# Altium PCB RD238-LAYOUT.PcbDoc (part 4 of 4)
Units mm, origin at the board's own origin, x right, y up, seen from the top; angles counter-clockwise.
Board outline 100 x 120 mm, 4 copper layers (Top Layer, GND2, POWER 3, Bottom Layer), stack 1.444 mm thick; 434 components, 174 nets, 1045 pads, 261 vias.
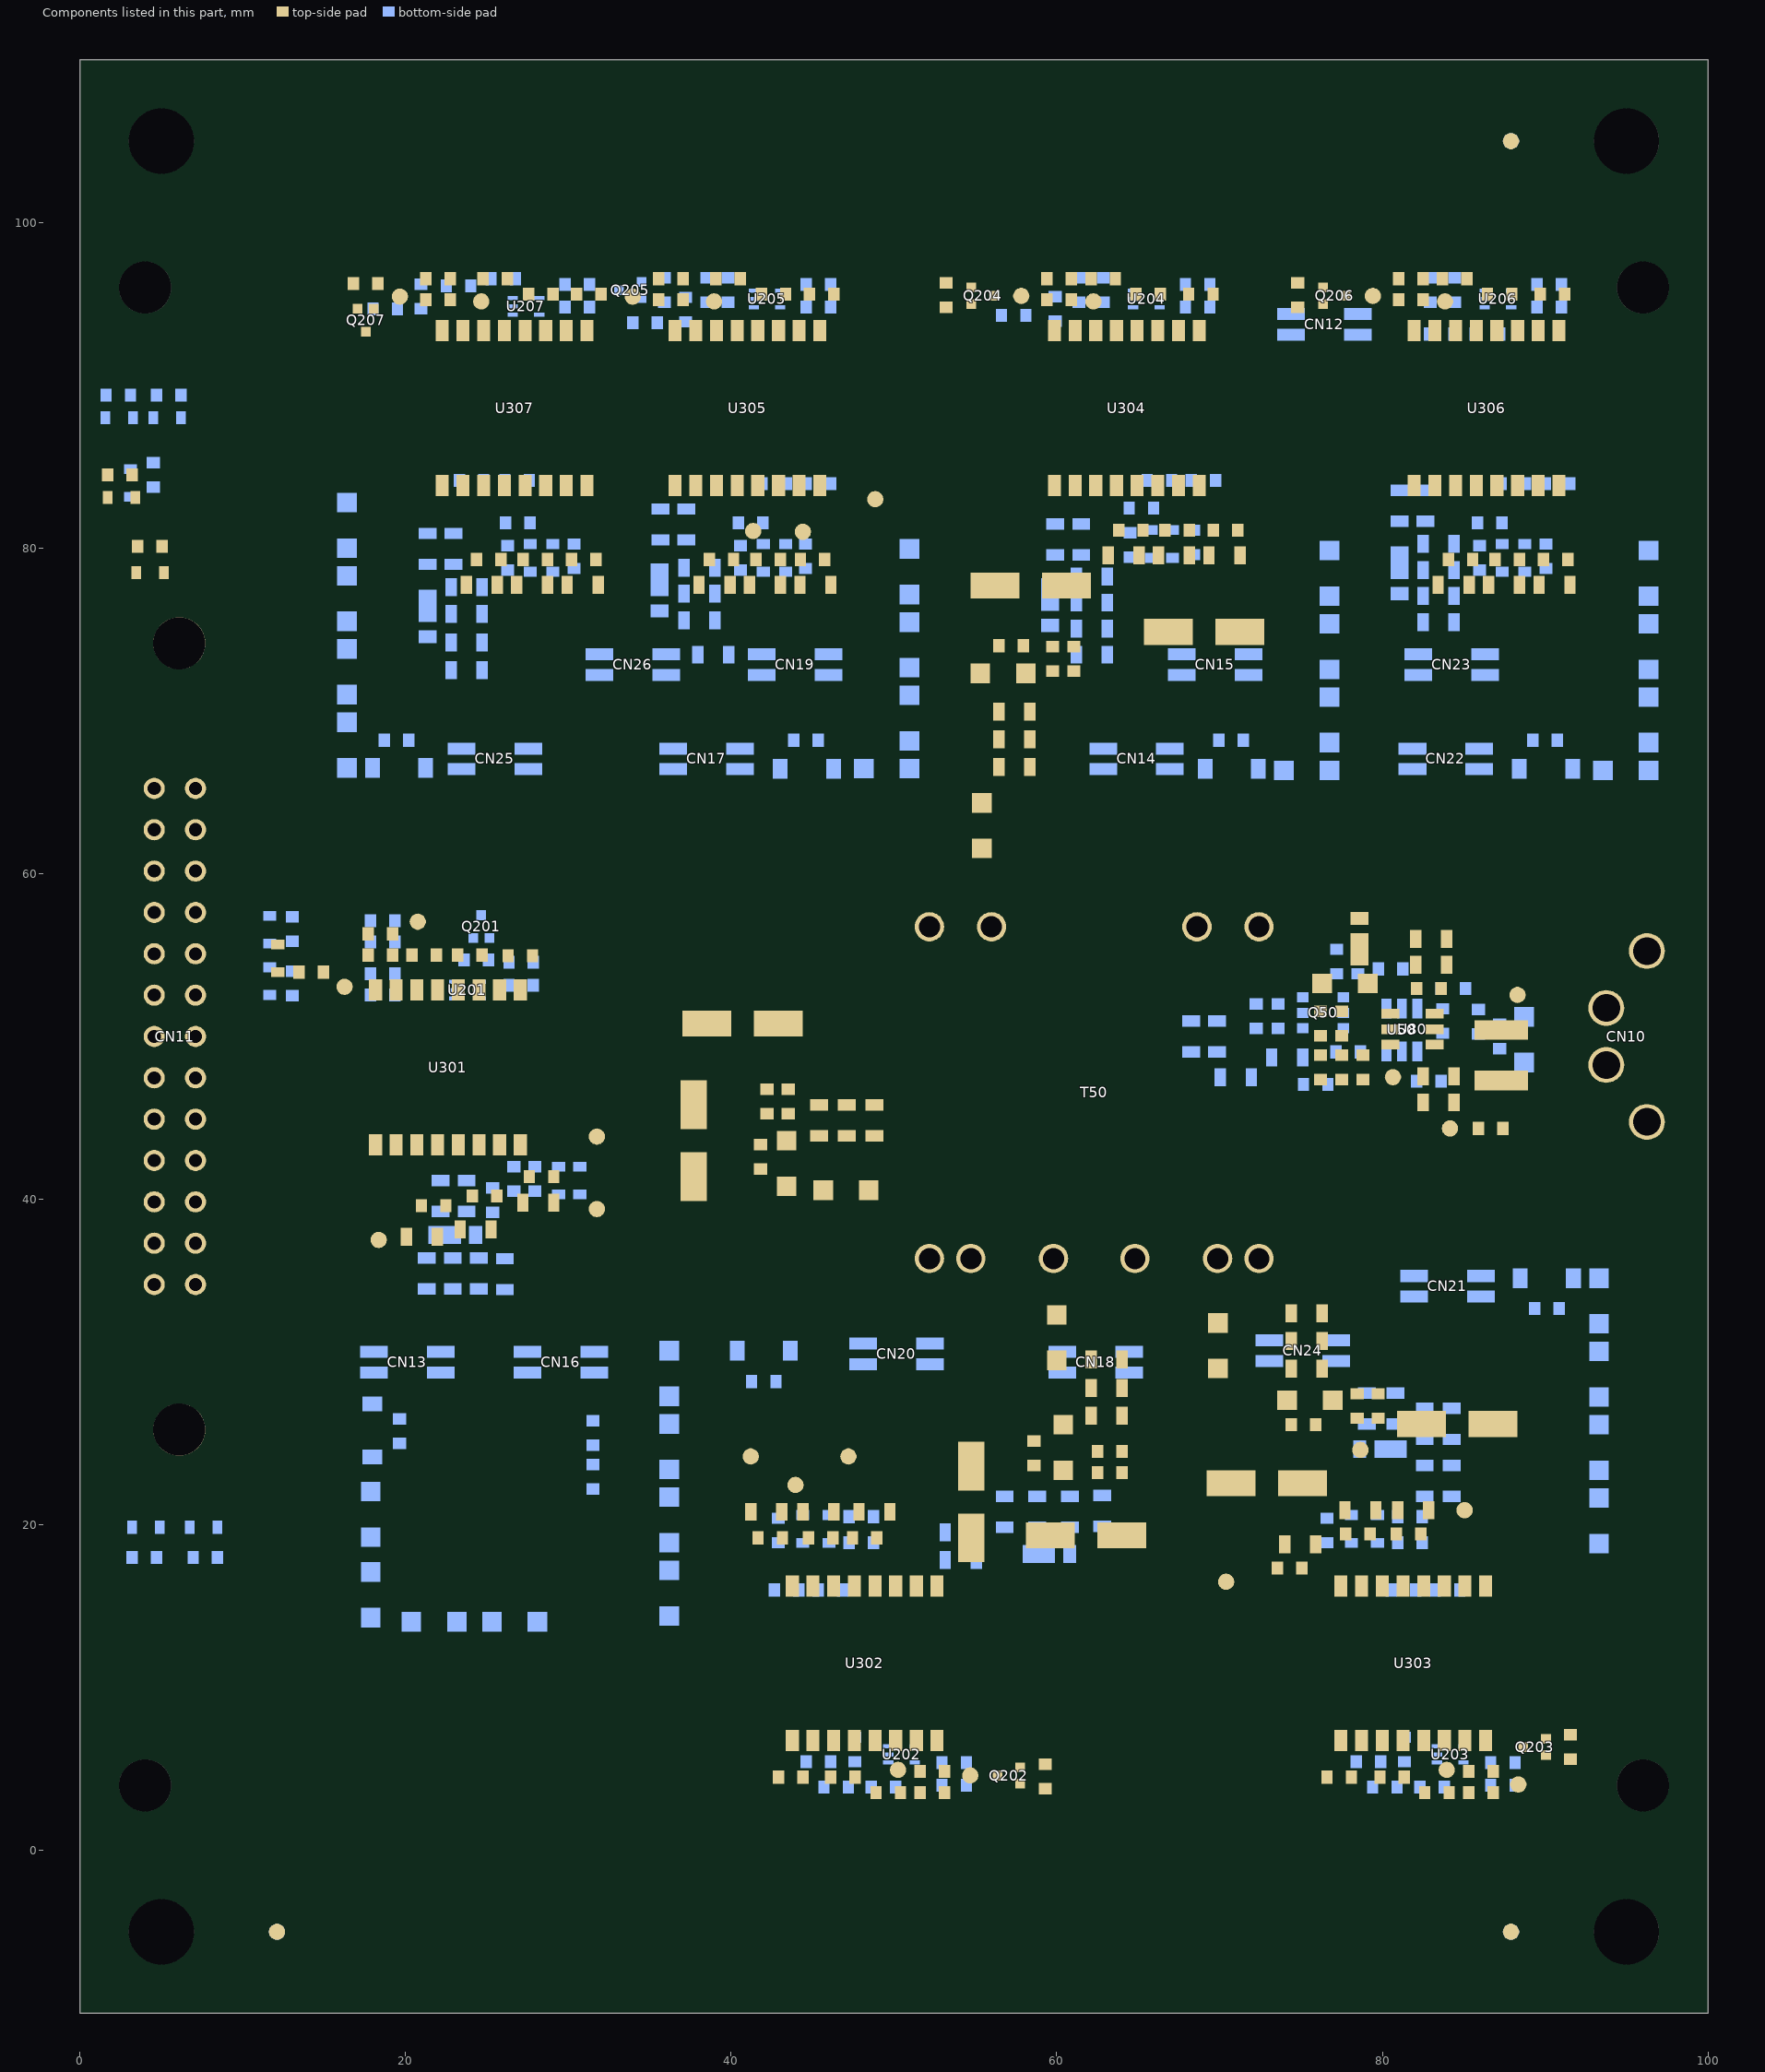
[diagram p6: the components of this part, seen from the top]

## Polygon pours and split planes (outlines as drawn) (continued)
NetD326_2 on Bottom Layer "NONET_L04_P-001" (solid, remove dead copper, pour order 385): 91.3,65.9 91.45,65.75 94,65.75 94.15,65.9 94.15,67.8 93.3,68.65 90.641,68.65 90.473,68.482 90.473,67.927 90.65,67.75 91.1,67.75 91.3,67.55 91.3,67.25
GND on Bottom Layer "NONET_L04_P-001" (solid, remove dead copper, pour order 376): 24.35,56.45 22.9,56.45 22.8,56.35 22.8,55.75 22,54.95 22,53.9 22.2,53.7 23.55,53.7 23.9,54.05 23.9,55.3 24.45,55.85 24.45,56.35
GND on Bottom Layer "NONET_L04_P-001" (solid, remove dead copper, pour order 375): 21 vertices, not listed, extent 10.05,53.45 18.15,56.2
NetR301_1 on Bottom Layer "NONET_L04_P-001" (solid, remove dead copper, pour order 369): 19 vertices, not listed, extent 19.7,40.25 27.05,43.8
NetC321_2 on Bottom Layer "NONET_L04_P-001" (solid, remove dead copper, pour order 368): 24 vertices, not listed, extent 24.95,37.2 31.2,40.8
NetD331_1 on Bottom Layer "NONET_L04_P-001" (solid, remove dead copper, pour order 365): 20.725,13.6 20.525,13.4 17.775,13.4 17.625,13.55 17.625,14.75 17.854,14.979 20.546,14.979 20.725,14.8
NetD341_1 on Bottom Layer "NONET_L04_P-001" (solid, remove dead copper, pour order 364): 25.575,13.6 25.475,13.5 23.025,13.5 22.875,13.65 22.875,14.6 22.975,14.7 25.475,14.7 25.575,14.6
NetD321_1 on Bottom Layer "NONET_L04_P-001" (solid, remove dead copper, pour order 363): 17.4,16.7 17.25,16.85 17.25,19.65 17.4,19.8 18.35,19.8 18.45,19.7 18.45,16.85 18.3,16.7
NetD342_1 on Bottom Layer "NONET_L04_P-001" (solid, remove dead copper, pour order 358): 35.7,16.75 35.6,16.85 35.6,19.3 35.75,19.45 36.7,19.45 36.8,19.35 36.8,16.85 36.7,16.75
NetD332_1 on Bottom Layer "NONET_L04_P-001" (solid, remove dead copper, pour order 357): 35.7,21.25 35.6,21.35 35.6,23.8 35.75,23.95 36.7,23.95 36.8,23.85 36.8,21.35 36.7,21.25
NetD322_1 on Bottom Layer "NONET_L04_P-001" (solid, remove dead copper, pour order 356): 35.7,25.75 35.6,25.85 35.6,28.3 35.75,28.45 36.7,28.45 36.8,28.35 36.8,25.85 36.7,25.75
NetD322_2 on Bottom Layer "NONET_L04_P-001" (solid, remove dead copper, pour order 355): 40.4,31.6 40.8,31.2 40.8,29.891 41.5,29.191 41.5,28.5 41.4,28.4 40.05,28.4 38.35,30.1 35.7,30.1 35.55,30.25 35.55,31.35 35.8,31.6
NetD323_2 on Bottom Layer "NONET_L04_P-001" (solid, remove dead copper, pour order 342): 93.75,35.8 93.9,35.65 93.9,34.65 93.8,34.55 92.7,34.55 92.25,34.1 92.25,33.55 91.6,32.9 90.6,32.9 90.5,33 90.5,33.65 91.25,34.4 91.25,35.7 91.35,35.8 91.4,35.8
NetCN21_1 on Bottom Layer "NONET_L04_P-001" (solid, remove dead copper, pour order 341): 88.8,35.75 88.9,35.65 88.9,34.25 89.2,33.95 89.5,33.95 89.65,33.8 89.65,32.95 89.45,32.75 81.45,32.75 81.05,33.15 81.05,35.55 81.25,35.75
NetR303_1 on Bottom Layer "NONET_L04_P-001" (solid, remove dead copper, pour order 339): 86.05,22.1 86.5,21.65 86.5,17.75 85.9,17.15 84.5,17.15 82.5,17.15 81.95,17.7 81.95,22 82.05,22.1
NetD343_1 on Bottom Layer "NONET_L04_P-001" (solid, remove dead copper, pour order 287): 92.8,21.2 92.7,21.3 92.7,23.75 92.85,23.9 93.8,23.9 93.9,23.8 93.9,21.3 93.8,21.2
NetD333_1 on Bottom Layer "NONET_L04_P-001" (solid, remove dead copper, pour order 286): 92.8,25.7 92.7,25.8 92.7,28.25 92.85,28.4 93.8,28.4 93.9,28.3 93.9,25.8 93.8,25.7
NetD323_1 on Bottom Layer "NONET_L04_P-001" (solid, remove dead copper, pour order 285): 92.8,30.2 92.7,30.3 92.7,32.75 92.85,32.9 93.8,32.9 93.9,32.8 93.9,30.3 93.8,30.2
GND on Bottom Layer "NONET_L04_P-001" (solid, remove dead copper, pour order 185): 4.65,20.15 4.65,18.9 4.4,18.65 4.4,17.8 4.65,17.55 6.95,17.55 7.3,17.9 7.3,18.7 7.05,18.95 7.05,20.1 6.85,20.3 4.8,20.3
NetC221_2 on POWER 3 "NONET_L04_P-001" (solid, remove dead copper, pour order 264): 23 vertices, not listed, extent 85.25,0.5 99.15,57.7
NetC334_2 on POWER 3 "2" (solid, remove dead copper, pour order 229): 41 vertices, not listed, extent 25.25,71.2 92.65,85
NetC221_2 on POWER 3 "NONET_L04_P-001" (solid, remove dead copper, pour order 473): 59 vertices, not listed, extent 0.95,1 90.7,99.05
NetC221_2 on POWER 3 "NONET_L04_P-001" (solid, remove dead copper, pour order 216): 26.7,52.05 27.5,52.85 27.5,56.35 27.2,56.65 27.18,56.63 24.461,56.63 22.182,54.35 16.3,54.35 12.875,57.775 12.85,57.7 12.85,52.25 13.05,52.05
no net on POWER 3 "NONET_L03_P613" (solid, pour order 613): 1,109 1,101 99,101 99,109
no net on POWER 3 "NONET_L03_P608" (solid, pour order 608): 1,-1 1,-9 99,-9 99,-1
NetC321_2 on POWER 3 "NONET_L04_P-001" (solid, remove dead copper, pour order 479): 18 vertices, not listed, extent 17.55,30.25 35.45,46
NetC324_1 on POWER 3 "NONET_L04_P-001" (solid, remove dead copper, pour order 234): 18 vertices, not listed, extent 57.15,73.9 73,82
NetC10_2 on POWER 3 "NONET_L04_P-001" (solid, remove dead copper, pour order 263): 82.1,49 84.5,51.4 87.6,51.4 88,51.8 88,55.9 87.4,56.5 82.85,56.5 81.4,55.05 68.2,55.05 67.45,54.3 67.45,50.675 69.125,49
NetC322_2 on POWER 3 "NONET_L04_P-001" (solid, remove dead copper, pour order 180): 43.1,16.2 43.8,15.5 58,15.5 58.55,16.05 58.55,20.9 54.4,25.05 43.45,25.05 43.1,24.7 43.1,24.6
NetC333_2 on POWER 3 "NONET_L04_P-001" (solid, remove dead copper, pour order 167): 70.35,25 68.85,23.5 68.85,16.4 69.75,15.5 82.25,15.5 82.9,16.15 82.9,24.15 82.05,25
GND on GND2 "NONET_L04_P-001" (solid, remove dead copper, pour order 461): 66 vertices, not listed, extent 1.7,1.95 99.1,61.6
NetC322_1 on GND2 "NONET_L04_P-001" (solid, remove dead copper, pour order 179): 65.85,20.15 65.85,15.8 65.55,15.5 43.6,15.5 40.1,19 40.1,23.6 40.8,24.3 54.25,24.3 58.05,20.5 65.5,20.5
GND on GND2 "GND_L02_P689" (solid, pour order 689): 77.45,57.7 77.2,57.45 77.2,55 78.85,55 79.65,55.8 83.8,55.8 84.8,56.8 87.2,56.8 88.15,55.85 90.25,55.85 90.65,56.25 90.65,57.45 90.4,57.7
NetC324_2 on GND2 "NONET_L04_P-001" (solid, remove dead copper, pour order 462): 33 vertices, not listed, extent 28.55,71.2 92.65,85
GND on GND2 "NONET_L04_P-001" (solid, remove dead copper, pour order 460): 33 vertices, not listed, extent 1,54.25 92.293,98.225
NetC10_2 on GND2 "NETC10_2_L02_P684" (solid, remove dead copper, pour order 684): 87,53.6 87.2,53.4 87.2,51.75 86.95,51.5 80.75,51.5 80.2,52.05 80.2,53.309 80.491,53.6
no net on GND2 "NONET_L02_P612" (solid, pour order 612): 1,109 1,101 99,101 99,109
no net on GND2 "NONET_L02_P610" (solid, pour order 610): 1,-1 1,-9 99,-9 99,-1
NetC321_1 on GND2 "NONET_L04_P-001" (solid, remove dead copper, pour order 475): 18 vertices, not listed, extent 17.15,34.05 42.7,56.85
NetC324_1 on GND2 "NONET_L04_P-001" (solid, remove dead copper, pour order 452): 64.2,74.15 63.85,73.8 63.85,72 64.25,71.6 73.17,71.6 73.35,71.78 73.35,78.3 72.75,78.9 71.05,78.9 70.65,78.5 70.65,75.2 69.6,74.15
NetC323_1 on GND2 "NONET_L04_P-001" (solid, remove dead copper, pour order 166): 85.6,21.8 85.6,23.55 85.948,23.898 89.202,23.898 89.55,23.55 89.55,16.4 88.75,15.6 71.85,15.6 71.4,16.05 71.4,19.85 72.75,21.2 85,21.2

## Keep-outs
Keep-Out Layer:
  circle w0.1: c59.8,36.36 r4
  circle w0.1: c64.8,36.36 r4
  circle w0.1: c69.88,36.36 r4
  circle w0.1: c72.42,36.36 r4
  circle w0.1: c52.18,56.74 r4
  circle w0.1: c55.99,56.74 r4
  circle w0.1: c52.18,36.36 r4
  circle w0.1: c72.42,56.74 r4
  circle w0.1: c68.61,56.74 r4
  circle w0.1: c5,105 r3
  circle w0.1: c5,-5 r3
  circle w0.1: c95,-5 r3
  circle w0.1: c95,105 r3
  circle w0.1: c93.75,51.75 r4.3
  circle w0.1: c93.75,48.25 r4.3
  circle w0.1: c4.56,65.24 r3.7
  circle w0.1: c7.1,65.24 r3.7
  circle w0.1: c7.1,57.62 r3.7
  circle w0.1: c7.1,55.08 r3.7
  circle w0.1: c6.1,74.15 r2.1
  circle w0.1: c96.25,55.25 r1.35
  circle w0.1: c96.25,44.75 r1.35
  circle w0.1: c4,4 r4
  circle w0.1: c96,4 r4
  circle w0.1: c4,4 r2.4
  circle w0.1: c96,4 r2.4
  circle w0.1: c96,96 r2.4
  circle w0.1: c96,96 r4
  circle w0.1: c4,96 r2.4
  circle w0.1: c4,96 r4
  lines w1: 0.5,-0.5 99.5,-0.5 ; 0.5,0.5 99.5,0.5 ; 0.5,99.51 99.5,99.51 ; 0.5,100.5 99.5,100.5 ; 23.05,31.55 23.148,31.545 23.34,31.507 23.521,31.432 23.684,31.323 23.823,31.184 23.932,31.021 24.007,30.84 24.045,30.648 24.05,30.55 24.05,18.247 ; 23.05,31.55 23.05,31.55 ; 23.05,31.55 13.868,31.55 13.614,31.618 13.386,31.749 13.199,31.936 13.068,32.164 13,32.418 13,32.682 13.068,32.936 13.199,33.164 13.386,33.351 13.614,33.482 13.868,33.55 14,33.55 23.05,33.55 23.247,33.55 23.637,33.499 24.017,33.397 24.38,33.247 24.72,33.05 25.033,32.811 25.311,32.533 25.55,32.22 25.747,31.88 25.897,31.517 25.999,31.137 26.05,30.747 26.05,30.55 ; 24.05,18.247 24.05,18.051 24.101,17.661 24.203,17.281 24.354,16.918 24.551,16.578 24.79,16.266 25.068,15.989 25.38,15.749 25.721,15.553 26.084,15.403 26.464,15.301 26.853,15.25 29.199,15.25 29.392,15.288 29.574,15.363 29.738,15.473 29.877,15.612 29.987,15.776 30.062,15.958 30.1,16.151 30.1,16.25 30.1,16.349 30.062,16.542 29.987,16.724 29.877,16.888 29.738,17.027 29.574,17.137 29.392,17.212 29.199,17.25 27.05,17.25 26.952,17.255 26.76,17.293 26.579,17.368 26.416,17.477 26.277,17.616 26.168,17.779 26.093,17.96 26.055,18.152 26.05,18.25 26.05,30.55 ; 24.05,18.247 24.05,18.247 ; 26.05,30.55 26.05,30.55 ; 35,31.252 35.005,31.349 35.044,31.541 35.119,31.722 35.228,31.885 35.366,32.023 35.529,32.132 35.71,32.207 35.902,32.245 36,32.25 36.5,32.25 36.599,32.25 36.792,32.288 36.974,32.363 37.138,32.473 37.277,32.612 37.387,32.776 37.462,32.958 37.5,33.151 37.5,33.25 37.5,33.349 37.462,33.542 37.387,33.724 37.277,33.888 37.138,34.027 36.974,34.137 36.792,34.212 36.599,34.25 36,34.25 35.997,34.25 ; 35,31.252 35,31.252 ; 35,31.252 35,11.4 35,11.268 34.932,11.014 34.801,10.786 34.614,10.599 34.386,10.468 34.132,10.4 33.868,10.4 33.614,10.468 33.386,10.599 33.199,10.786 33.068,11.014 33,11.268 33,11.4 33,31.25 33,31.447 33.051,31.836 33.153,32.216 33.303,32.579 33.499,32.92 33.739,33.232 34.016,33.51 34.328,33.749 34.668,33.946 35.031,34.097 35.411,34.199 35.801,34.25 35.997,34.25 ; 35.997,34.25 35.997,34.25 ; 37.615,24.518 37.615,16.9 37.615,16.768 37.683,16.514 37.814,16.286 38.001,16.099 38.229,15.968 38.483,15.9 38.747,15.9 39.001,15.968 39.229,16.099 39.416,16.286 39.547,16.514 39.615,16.768 39.615,16.9 39.615,24.65 39.62,24.748 39.658,24.94 39.733,25.121 39.842,25.284 39.981,25.423 40.144,25.532 40.325,25.607 40.517,25.645 40.615,25.65 40.714,25.65 ; 37.615,24.518 37.615,24.518 ; 37.615,24.518 37.615,24.65 37.615,24.847 37.615,24.85 37.615,24.982 37.65,25.112 37.666,25.237 37.768,25.617 37.918,25.98 38.115,26.32 38.354,26.633 38.632,26.911 38.945,27.15 39.285,27.347 39.648,27.497 40.028,27.599 40.418,27.65 40.483,27.65 ; 40.483,27.65 40.483,27.65 ; 40.483,27.65 52.468,27.65 ; 40.714,25.65 52.699,25.65 ; 40.714,25.65 40.714,25.65 ; 46.803,69.2 46.999,69.2 47.389,69.251 47.769,69.353 48.132,69.504 48.472,69.701 48.784,69.94 49.061,70.218 49.301,70.53 49.497,70.871 49.647,71.234 49.749,71.614 49.8,72.003 49.8,72.2 49.782,72.2 49.8,72.268 49.8,72.4 49.8,80.303 49.8,80.435 49.732,80.689 49.6,80.917 49.414,81.103 49.186,81.235 48.932,81.303 48.668,81.303 48.414,81.235 48.186,81.103 47.999,80.917 47.868,80.689 47.8,80.435 47.8,80.303 47.8,72.4 47.8,72.268 47.818,72.2 47.8,72.2 ; 46.803,69.2 46.803,69.2 ; 46.803,69.2 46.8,69.2 34.5,69.2 34.5,64.7 34.5,64.568 34.432,64.314 34.3,64.086 34.114,63.899 33.886,63.768 33.632,63.7 33.368,63.7 33.114,63.768 32.886,63.899 32.699,64.086 32.568,64.314 32.5,64.568 32.5,64.7 32.5,69.2 20.694,69.2 20.537,69.19 20.16,69.215 19.789,69.289 19.432,69.411 19.093,69.578 18.779,69.789 18.495,70.038 18.246,70.323 18.037,70.637 17.87,70.976 17.749,71.334 17.675,71.705 17.67,71.795 17.661,71.826 17.661,71.926 17.655,72.025 17.661,72.057 17.661,82.55 17.661,82.682 17.729,82.936 17.861,83.164 18.047,83.351 18.275,83.482 18.53,83.55 18.793,83.55 19.048,83.482 19.276,83.351 19.462,83.164 19.594,82.936 19.662,82.682 19.662,82.55 19.662,72.004 19.67,71.936 19.714,71.769 19.791,71.614 19.896,71.476 20.026,71.362 20.175,71.276 20.339,71.22 20.511,71.197 20.518,71.197 20.53,71.2 20.629,71.2 20.7,71.205 20.732,71.2 46.8,71.2 46.898,71.205 47.09,71.243 47.271,71.318 47.434,71.427 47.573,71.566 47.682,71.729 47.757,71.91 47.795,72.102 47.8,72.2 ; 47.8,72.2 47.8,72.2 ; 52.468,27.65 52.468,27.65 ; 52.468,27.65 52.6,27.65 52.698,27.655 52.89,27.693 53.071,27.768 53.234,27.877 53.373,28.016 53.482,28.179 53.557,28.36 53.595,28.552 53.6,28.65 53.6,28.782 53.6,32.054 47.468,32.054 47.214,32.122 46.986,32.253 46.799,32.44 46.668,32.668 46.6,32.922 46.6,33.186 46.668,33.44 46.799,33.668 46.986,33.855 47.214,33.986 47.468,34.054 55.277,34.054 55.375,34.059 55.568,34.097 55.749,34.172 55.911,34.281 56.05,34.42 56.159,34.583 56.234,34.764 56.272,34.956 56.277,35.054 ; 52.699,25.65 52.797,25.65 53.187,25.701 53.567,25.803 53.93,25.953 54.27,26.15 54.583,26.389 54.861,26.667 55.1,26.98 55.297,27.32 55.447,27.683 55.549,28.063 55.6,28.453 55.6,28.518 ; 52.699,25.65 52.699,25.65 ; 55.6,28.518 55.6,28.65 55.6,32.07 55.866,32.105 56.246,32.207 56.609,32.358 56.949,32.555 57.261,32.794 57.539,33.072 57.778,33.384 57.974,33.725 58.125,34.088 58.226,34.468 58.278,34.857 58.278,35.054 58.278,48.25 58.278,48.382 58.21,48.636 58.078,48.864 57.892,49.051 57.663,49.182 57.409,49.25 57.146,49.25 56.891,49.182 56.663,49.051 56.477,48.864 56.345,48.636 56.277,48.382 56.277,48.25 56.277,35.054 ; 55.6,28.518 55.6,28.518 ; 56.277,35.054 56.277,35.054 ; 62.397,71.2 62.201,71.2 61.811,71.149 61.431,71.047 61.068,70.896 60.728,70.699 60.416,70.46 60.139,70.182 59.899,69.87 59.703,69.529 59.553,69.166 59.451,68.786 59.4,68.397 59.4,68.2 59.4,61.8 59.4,61.668 59.468,61.414 59.599,61.186 59.786,60.999 60.014,60.868 60.268,60.8 60.532,60.8 60.786,60.868 61.014,60.999 61.201,61.186 61.332,61.414 61.4,61.668 61.4,61.8 61.4,68.2 61.405,68.298 61.443,68.49 61.518,68.671 61.627,68.834 61.766,68.973 61.929,69.082 62.11,69.157 62.302,69.195 62.4,69.2 72.6,69.2 72.603,69.2 ; 62.397,71.2 62.397,71.2 ; 62.397,71.2 62.4,71.2 72.6,71.2 72.698,71.205 72.89,71.243 73.071,71.318 73.234,71.427 73.373,71.566 73.482,71.729 73.557,71.91 73.595,72.102 73.6,72.2 ; 72.603,69.2 72.799,69.2 73.189,69.251 73.569,69.353 73.932,69.504 74.272,69.701 74.584,69.94 74.861,70.218 75.101,70.53 75.297,70.871 75.447,71.234 75.549,71.614 75.6,72.003 75.6,72.2 75.582,72.2 75.6,72.268 75.6,72.4 75.6,80.8 75.6,80.932 75.532,81.186 75.401,81.414 75.214,81.601 74.986,81.732 74.732,81.8 74.468,81.8 74.214,81.732 73.986,81.601 73.799,81.414 73.668,81.186 73.6,80.932 73.6,80.8 73.6,72.4 73.6,72.268 73.618,72.2 73.6,72.2 ; 72.603,69.2 72.603,69.2 ; 73.6,72.2 73.6,72.2 ; 89.05,32.25 81.55,32.25 81.452,32.255 81.26,32.293 81.079,32.368 80.916,32.477 80.777,32.616 80.668,32.779 80.593,32.96 80.555,33.152 80.55,33.25 80.55,39.797 80.55,39.929 80.482,40.183 80.351,40.411 80.164,40.597 79.936,40.729 79.682,40.797 79.418,40.797 79.164,40.729 78.936,40.597 78.75,40.411 78.618,40.183 78.55,39.929 78.55,39.797 78.55,33.25 78.55,33.053 78.601,32.663 78.703,32.283 78.853,31.92 79.05,31.579 79.289,31.267 79.567,30.989 79.88,30.75 80.22,30.553 80.583,30.403 80.963,30.301 81.353,30.25 81.55,30.25 89.05,30.25 89.148,30.245 89.34,30.207 89.521,30.132 89.684,30.023 89.823,29.884 89.932,29.721 90.007,29.54 90.045,29.348 90.05,29.25 90.05,17.65 90.05,17.518 90.118,17.264 90.249,17.036 90.436,16.849 90.664,16.718 90.918,16.65 91.182,16.65 91.436,16.718 91.664,16.849 91.85,17.036 91.982,17.264 92.05,17.518 92.05,17.65 92.05,29.25 92.05,29.447 91.999,29.837 91.897,30.217 91.747,30.58 91.55,30.92 91.311,31.233 91.033,31.511 90.72,31.75 90.38,31.947 90.017,32.097 89.637,32.199 89.247,32.25 89.05,32.25 ; 89.05,32.25 89.05,32.25 ; 92.203,69.2 92.399,69.2 92.789,69.251 93.169,69.353 93.532,69.504 93.872,69.701 94.184,69.94 94.461,70.218 94.701,70.53 94.897,70.871 95.047,71.234 95.149,71.614 95.2,72.003 95.2,72.2 95.2,80.8 95.2,80.932 95.132,81.186 95.001,81.414 94.814,81.601 94.586,81.732 94.332,81.8 94.068,81.8 93.814,81.732 93.586,81.601 93.399,81.414 93.268,81.186 93.2,80.932 93.2,80.8 93.2,72.2 ; 92.203,69.2 92.203,69.2 ; 92.203,69.2 92.2,69.2 79.9,69.2 79.9,64.7 79.9,64.568 79.832,64.314 79.701,64.086 79.514,63.899 79.286,63.768 79.032,63.7 78.768,63.7 78.514,63.768 78.286,63.899 78.099,64.086 77.968,64.314 77.9,64.568 77.9,64.7 77.9,80.8 77.9,80.932 77.968,81.186 78.099,81.414 78.286,81.601 78.514,81.732 78.768,81.801 79.032,81.801 79.286,81.732 79.514,81.601 79.701,81.414 79.832,81.186 79.9,80.932 79.9,80.8 79.9,71.2 92.2,71.2 92.298,71.205 92.49,71.243 92.671,71.318 92.834,71.427 92.973,71.566 93.082,71.729 93.157,71.91 93.195,72.102 93.2,72.2 ; 92.449,10.623 92.588,10.762 96.157,14.332 96.227,14.401 96.337,14.565 96.412,14.747 96.45,14.94 96.45,15.039 96.45,36.45 96.45,36.549 96.412,36.742 96.337,36.924 96.227,37.088 96.157,37.157 ; 92.449,10.623 92.449,10.623 ; 92.449,10.623 92.425,10.599 92.34,10.55 92.285,10.513 92.254,10.501 92.197,10.468 92.133,10.451 92.103,10.438 92.038,10.425 91.943,10.4 87.918,10.4 87.664,10.468 87.436,10.599 87.249,10.786 87.118,11.014 87.05,11.268 87.05,11.532 87.118,11.786 87.249,12.014 87.436,12.201 87.664,12.332 87.918,12.4 91.397,12.4 94.45,15.453 94.45,36.036 91.396,39.089 91.303,39.183 91.171,39.411 91.103,39.665 91.103,39.929 91.171,40.183 91.303,40.411 91.489,40.597 91.717,40.729 91.971,40.797 92.235,40.797 92.489,40.729 92.717,40.597 92.811,40.504 96.157,37.157 ; 93.2,72.2 93.2,72.2 ; 96.157,37.157 96.157,37.157 ; 0,-10 0,110 100,110 100,-10 0,-10 ; 0.5,-9.5 99.5,-9.5 99.5,109.5 0.5,109.5 0.5,-9.5 ; 52.1,61.668 52.168,61.414 52.299,61.186 52.486,60.999 52.714,60.868 52.968,60.8 53.232,60.8 53.486,60.868 53.714,60.999 53.9,61.186 54.032,61.414 54.1,61.668 54.1,61.8 54.1,80.8 54.1,80.932 54.032,81.186 53.9,81.414 53.714,81.601 53.486,81.732 53.232,81.8 52.968,81.8 52.714,81.732 52.486,81.601 52.299,81.414 52.168,81.186 52.1,80.932 52.1,80.8 52.1,61.8 52.1,61.668 ; 66.35,13.118 66.418,12.864 66.549,12.636 66.736,12.449 66.964,12.318 67.218,12.25 67.482,12.25 67.736,12.318 67.964,12.449 68.151,12.636 68.282,12.864 68.35,13.118 68.35,13.25 68.35,41.9 68.35,42.032 68.282,42.286 68.151,42.514 67.964,42.701 67.736,42.832 67.482,42.9 67.218,42.9 66.964,42.832 66.736,42.701 66.549,42.514 66.418,42.286 66.35,42.032 66.35,41.9 66.35,13.25 66.35,13.118
  lines w3: 1.5,1.5 98.5,1.5 98.5,98.5 1.5,98.5
  lines w8: 13.15,12.1 15.85,9.4 39.686,9.4 41.786,11.5 88.05,11.5 ; 13.16,12.1 13.16,48.05 ; 13.2,48.1 29.4,48.1 32.65,51.35 32.65,61.75 ; 36.35,35.85 47.2,35.85 ; 46.7,61.8 46.7,55.05 51.25,50.5 62.85,50.5 ; 50.45,61.8 11.75,61.8 11.75,85.95 14.4,88.6 100.7,88.6 ; 92.103,39.797 76.903,39.797 74.6,42.1 62.9,42.1 62.9,61.7 100.8,61.7

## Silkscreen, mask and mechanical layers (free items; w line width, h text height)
Top Overlay:
  drawing of 530 lines, arcs and shapes, not listed
  text "RD238" at 39.438,59.475 h1.3
  text "A" at 82.25,34.15 h0.7
  text "A" at 76.15,34.1 h0.7
Bottom Overlay:
  drawing of 715 lines, arcs and shapes, not listed
Top Solder:
  drawing of 726 lines, arcs and shapes, not listed
Bottom Solder:
  drawing of 726 lines, arcs and shapes, not listed
Mechanical 2:
  lines w0.1: 0,0 100,0
outline:
  drawing of 742 lines, arcs and shapes, not listed
  text "V-CUT" at 104.6,98.9 h0.7
  text "V-CUT" at 104.6,-1.1 h0.7
Drill Drawing:
  circle w0.254: c-46.894,121.99 r0.847
  lines w0.254: -47.741,126.647 -46.047,126.647 -46.894,124.953 -47.741,126.647 ; -47.741,128.763 -47.741,129.187 -47.317,129.61 -47.741,130.033 -47.741,130.457 -47.317,130.457 -46.894,130.033 -46.471,130.457 -46.047,130.457 -46.047,130.033 -46.471,129.61 -46.047,129.187 -46.047,128.763 -46.471,128.763 -46.894,129.187 -47.317,128.763 -47.741,128.763 ; -47.741,132.573 -46.047,132.573 -46.047,134.267 -47.741,134.267 -47.741,132.573 ; -47.741,136.807 -47.317,136.807 -47.317,136.383 -46.471,136.383 -46.471,136.807 -46.047,136.807 -46.047,137.653 -46.471,137.653 -46.471,138.077 -47.317,138.077 -47.317,137.653 -47.741,137.653 -47.741,136.807 ; -47.741,140.193 -46.894,140.617 -46.047,140.193 -46.471,141.04 -46.047,141.887 -46.894,141.463 -47.741,141.887 -47.317,141.04 -47.741,140.193 ; -47.741,144.427 -47.317,144.427 -46.894,144.003 -46.471,144.427 -46.047,144.427 -46.471,144.85 -46.047,145.273 -46.471,145.273 -46.894,145.697 -47.317,145.273 -47.741,145.273 -47.317,144.85 -47.741,144.427
  lines w0.381: -49.26,120 236.004,120 ; -49.26,146.67 236.004,146.67 ; -35.267,116.19 -35.267,150.48 ; -20.539,116.19 -20.539,150.48 ; 8.662,116.19 8.662,150.48 ; 21.512,116.19 21.512,150.48 ; 40.15,116.19 40.15,150.48 ; 78.239,116.19 78.239,150.48 ; 93.221,116.19 93.221,150.48 ; 112.164,116.19 112.164,150.48 ; 145.428,116.19 145.428,150.48 ; 167.114,116.19 167.114,150.48 ; 200.988,116.19 200.988,150.48 ; -49.26,116.19 236.004,116.19 236.004,150.48 -49.26,150.48 -49.26,116.19
  text "Count" at -34.124,147.813 h1.83
  text "Hole Size" at -19.396,147.813 h1.83
  text "Plated" at 9.805,147.813 h1.83
  text "Hole Type" at 22.655,147.813 h1.83
  text "Drill Layer Pair" at 41.293,147.813 h1.83
  text "Via/Pad" at 79.382,147.813 h1.83
  text "Pad Shape" at 94.364,147.813 h1.83
  text "Template" at 113.307,147.813 h1.83
  text "Description" at 146.571,147.813 h1.83
  text "Hole Tolerance (+)" at 168.257,147.813 h1.83
  text "Hole Tolerance (-)" at 202.131,147.813 h1.83
  text "2" at -34.124,144.003 h1.52
  text "125.98mil (3.200mm)" at -19.396,144.003 h1.52
  text "NPTH" at 9.805,144.003 h1.52
  text "Round" at 22.655,144.003 h1.52
  text "Top Layer - Bottom Layer" at 41.293,144.003 h1.52
  text "Pad" at 79.382,144.003 h1.52
  text "Rounded" at 94.364,144.003 h1.52
  text "c320hn320m370(Tol5-5)" at 113.307,144.003 h1.52
  text "1.97mil (0.050mm)" at 168.257,144.003 h1.52
  text "1.97mil (0.050mm)" at 202.131,144.003 h1.52
  text "4" at -34.124,140.193 h1.52
  text "66.93mil (1.700mm)" at -19.396,140.193 h1.52
  text "PTH" at 9.805,140.193 h1.52
  text "Round" at 22.655,140.193 h1.52
  text "Top Layer - Bottom Layer" at 41.293,140.193 h1.52
  text "Pad" at 79.382,140.193 h1.52
  text "Rounded" at 94.364,140.193 h1.52
  text "c220h170m225(Tol8-8)" at 113.307,140.193 h1.52
  text "3.15mil (0.080mm)" at 168.257,140.193 h1.52
  text "3.15mil (0.080mm)" at 202.131,140.193 h1.52
  text "4" at -34.124,136.383 h1.52
  text "125.98mil (3.200mm)" at -19.396,136.383 h1.52
  text "NPTH" at 9.805,136.383 h1.52
  text "Round" at 22.655,136.383 h1.52
  text "Top Layer - Bottom Layer" at 41.293,136.383 h1.52
  text "Pad" at 79.382,136.383 h1.52
  text "Rounded" at 94.364,136.383 h1.52
  text "c320hn320m370" at 113.307,136.383 h1.52
  text "4" at -34.124,132.573 h1.52
  text "157.48mil (4.000mm)" at -19.396,132.573 h1.52
  text "NPTH" at 9.805,132.573 h1.52
  text "Round" at 22.655,132.573 h1.52
  text "Top Layer - Bottom Layer" at 41.293,132.573 h1.52
  text "Pad" at 79.382,132.573 h1.52
  text "Rounded" at 94.364,132.573 h1.52
  text "c400hn400m450" at 113.307,132.573 h1.52
  text "10" at -34.124,128.763 h1.52
  text "51.18mil (1.300mm)" at -19.396,128.763 h1.52
  text "PTH" at 9.805,128.763 h1.52
  text "Round" at 22.655,128.763 h1.52
  text "Top Layer - Bottom Layer" at 41.293,128.763 h1.52
  text "Pad" at 79.382,128.763 h1.52
  text "Rounded" at 94.364,128.763 h1.52
  text "c180h130m185(Tol8-8)" at 113.307,128.763 h1.52
  text "2.95mil (0.075mm)" at 168.257,128.763 h1.52
  text "2.95mil (0.075mm)" at 202.131,128.763 h1.52
  text "26" at -34.124,124.953 h1.52
  text "31.50mil (0.800mm)" at -19.396,124.953 h1.52
  text "PTH" at 9.805,124.953 h1.52
  text "Round" at 22.655,124.953 h1.52
  text "Top Layer - Bottom Layer" at 41.293,124.953 h1.52
  text "Pad" at 79.382,124.953 h1.52
  text "Rounded" at 94.364,124.953 h1.52
  text "c130h80m135(Tol10-0)" at 113.307,124.953 h1.52
  text "3.94mil (0.100mm)" at 168.257,124.953 h1.52
  text "0.00mil (0.000mm)" at 202.131,124.953 h1.52
  text "261" at -34.124,121.143 h1.52
  text "15.75mil (0.400mm)" at -19.396,121.143 h1.52
  text "PTH" at 9.805,121.143 h1.52
  text "Round" at 22.655,121.143 h1.52
  text "Top Layer - Bottom Layer" at 41.293,121.143 h1.52
  text "Via" at 79.382,121.143 h1.52
  text "Rounded" at 94.364,121.143 h1.52
  text "v80h40m70" at 113.307,121.143 h1.52
  text "311 Total" at -34.124,117.333 h1.52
